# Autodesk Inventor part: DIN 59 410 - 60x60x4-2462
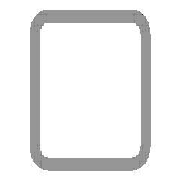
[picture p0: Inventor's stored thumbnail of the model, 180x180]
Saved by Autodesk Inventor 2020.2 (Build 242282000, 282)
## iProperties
Manager: www.cadconsulting.pl
Company: Fabian Stasiak CAD Consulting
IsCustomPart: 1
_CCFamilyMember: 60
_CCFamilyDisplayName: DIN 59410 (Kwadrat) - Rurki stalowe o przekroju kwadratowym formowane na gorąco
_FrameMemberDoc: Frame Member File
_Version: 15.0.0
_GetPNFromCC: 1
Created: 2015-01
Part Number: DIN 59 410 - 60x60x4-2462
Material: Stal, miękka
Description: Rurki stalowe o przekroju kwadratowym formowane na gorąco
Document SubType Name: Modellieren
Standard: DIN
Designer: F.Stasiak
Standards Organization: DIN
Language: pl-PL
Size Designation: 60x60x4
Categories: <MemberInstance><Categories><Category DisplayName="Kształtowniki konstrukcyjne" InternalName="089c4875-fa83-4c05-b084-43b9cc11f5ed" Mnemonic="GRDR"><CategoryPar
Stock Number: 60x60x4
Density: 7.85 g/cm^3
Appearance: Częściowo polerowana
Catalog Web Link: www.expertbooks.pl
G_L: 2462,000 mm
G_W: 60,000 mm
G_H: 60,000 mm
+DD02B62E-7EF7-4818-BB21-446099D65FF9+CUTDETAIL1: Wytnij
Author: F.Stasiak
Subject: Zbiór ćwiczeń. Autodesk Inventor 2020. Kurs Professional
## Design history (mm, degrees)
node "Płaszczyzna początkowa"
node "Płaszczyzna końcowa"
sketch "Szkic1"
  geometry: L1 (-22, 30)-(22, 30); L2 (30, 22)-(30, -22); L3 (22, -30)-(-22, -30); L4 (-30, -22)-(-30, 22); L5 (-44.32, 0)-(44.32, 0) reference; L6 (0, -44.32)-(0, 44.32) reference; L7 (-22, 26)-(22, 26); L8 (26, 22)-(26, -22); L9 (22, -26)-(-22, -26); L10 (-26, -22)-(-26, 22); A1 r 8 centre (-22, 22) between (-22, 30) and (-30, 22); A2 r 8 centre (22, 22) between (30, 22) and (22, 30); A3 r 8 centre (22, -22) between (22, -30) and (30, -22); A4 r 8 centre (-22, -22) between (-30, -22) and (-22, -30); A5 r 4 centre (-22, 22) between (-22, 26) and (-26, 22); A6 r 4 centre (22, 22) between (26, 22) and (22, 26); A7 r 4 centre (22, -22) between (22, -26) and (26, -22); A8 r 4 centre (-22, -22) between (-26, -22) and (-22, -26); 3 further points
  constraints: 16 end point, 16 point on circle, 8 centre point, 8 tangent, 6 point on line, 4 parallel, 3 equal radius, 3 perpendicular, 1 horizontal, 7 other
  dimensions: "b" = 60 distance of point (-30, 30) point (30, 30); "msp_r" = 8 radius of A1 (= 2 x ParT); "d8" = 30 distance between parallel lines of L4 L6 (= d9); "d9" = 30 distance between parallel lines of L3 L5 (= 0.5 x b); "d10" = 4 distance between parallel lines of L3 L9 (= ParT)
extrude "Bryła" new body sketch "Szkic1" taper "d4" = 0 deg; stored distance "NLG" = 10
node "Driven Length"
  sketch "Sketch2"
    geometry: L1 (0, 0)-(10, 0) reference
    constraints: 2 end point, 1 horizontal
  workplane "Work Plane3"
  sketch "Sketch3"
    geometry: L1 (-2, 0)-(12, 0) reference; L2 (-2, 2462)-(12, 2462) reference
    dimensions: "d14" = 2462 distance between parallel lines of L1 L2 (derived)
node "Płaszczyzna konstrukcyjna4"
feature "Podział1"
body "Solid1"
other parameters: "ParT" = 4, "G_OFFSET_START" = 0 [user parameter; used in 1 equation term], "G_OFFSET_END" = -38 [user parameter; used in 1 equation term], "d11" = 0 (computed from G_OFFSET_START), "d12" = 2462 (= G_OFFSET_END + B_L), "G_L" = 2462 (= d14) [user parameter], "d13" = 90 deg
